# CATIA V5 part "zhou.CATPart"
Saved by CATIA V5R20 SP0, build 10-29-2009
Part number: 轴
Bounding box of the stored display mesh (mm): x -65 to 65, y -64.818 to 64.818, z -717 to 2
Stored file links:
  E:\3D工程制图作业\Part2.CATPart
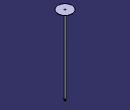
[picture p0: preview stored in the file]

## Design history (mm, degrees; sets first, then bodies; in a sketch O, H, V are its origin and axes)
Body1 (main body)
  Sketch1 on xy-plane, origin (0, 0, 0), H (1, 0, 0), V (0, 1, 0)
    circle A1 centre (0, 0) radius 65
    radius A1 = 65
  Pad1: profile Sketch1, direction (0, 0, 1), length 2
  Sketch2 on xy-plane, origin (0, 0, 0), H (1, 0, 0), V (0, 1, 0)
    circle A1 centre (0, 0) radius 6
    radius A1 = 6
  Pad2: profile Sketch2, direction (0, 0, -1), length 700
  Plane1: type Offset, RefPlane xy-plane, Offset 80
  DatumSurface1
  DatumSurface2
  Sketch3 on face of Pad2, origin (0, 0, -700), H (1, 0, 0), V (0, -1, 0)
    line L1 (3.1231, 7.5804) -> (3.1231, -7.4196)
    line L2 (3.1231, -7.4196) -> (0.1231, -7.4196)
    point P3 (0.1231, -7.4196)
    line L3 (0.1231, -7.4196) -> (0.1231, 7.5804)
    point P4 (0.1231, 7.5804)
    line L4 (0.1231, 7.5804) -> (3.1231, 7.5804)
    distance P3 P4 = 15
    length L4 = 3
    vertical: L1 V, L3 V
    horizontal: L2 H, L4 H
  Pad3: profile Sketch3, direction (0, 0, -1), length 17
  Sketch4 on face of Pad3 from Sketch3.L3, origin (0.1231, -0.7113, -709.2076), H (0, -1, 0), V (0, 0, 1)
    point P1 (-0.6309, -0.6182)
    reference projected line E1 (-8.1309, -7.7924) -> (-8.1309, 9.2076) from edge [face of Pad3 from Sketch3.L3 | face of Pad3 from Sketch3.L2]
    distance P1 E1 = 7.5
  Hole1: placed by Sketch4, at (0.1231, -0.0804, -709.8258) direction (1, 0, 0), diameter 10, depth 10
